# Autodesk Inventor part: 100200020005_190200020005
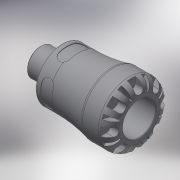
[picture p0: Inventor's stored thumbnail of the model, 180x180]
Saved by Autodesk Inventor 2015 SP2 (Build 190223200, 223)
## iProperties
Created: 2016-12
Part Number: 100200020005_190200020005
Material: Generic
Description: PLASSON MALE ADAPTOR 20X1/2" SERIES 1
Document SubType Name: Modeling
Designer: KIM
Mass: 447.839 g
Surface Area: 722.341 cm^2
Volume: 447.839 cm^3
Density: 1 g/cm^3
Appearance: Default
Author: KIM
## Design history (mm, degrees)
derived "1002.ipt"
feature "Solid1::1002.ipt"
tag "TaggingFeature1"
body "Solid1"
other parameters: "d1" = 18.9, "d3" = 25, "d4" = 41, "d6" = 45, "d8" = 34.85, "d13" = 6.4, "d14" = 6.4, "d15" = 0, "d17" = 360 deg, "d19" = 8 deg, "d20" = 0.4, "d21" = 0.4, "d22" = 8 deg, "d24" = 0, "d26" = 360 deg, "d32" = 0.925, "d33" = 4.1, "d34" = 20.955, "d35" = 2.5, "d38" = 16, "d39" = 0.62865, "d42" = 7, "d43" = 4.6, "d45" = 12.544, "d46" = 0, "d59" = 360 deg, "d61" = 5.95, "d62" = 0.4, "d64" = 0, "d65" = 0.41, "E_" = 41, "l_" = 45, "R_" = 20.955, "l_2" = 16, "d9" = 8, "d11" = 41, "d12" = 25
